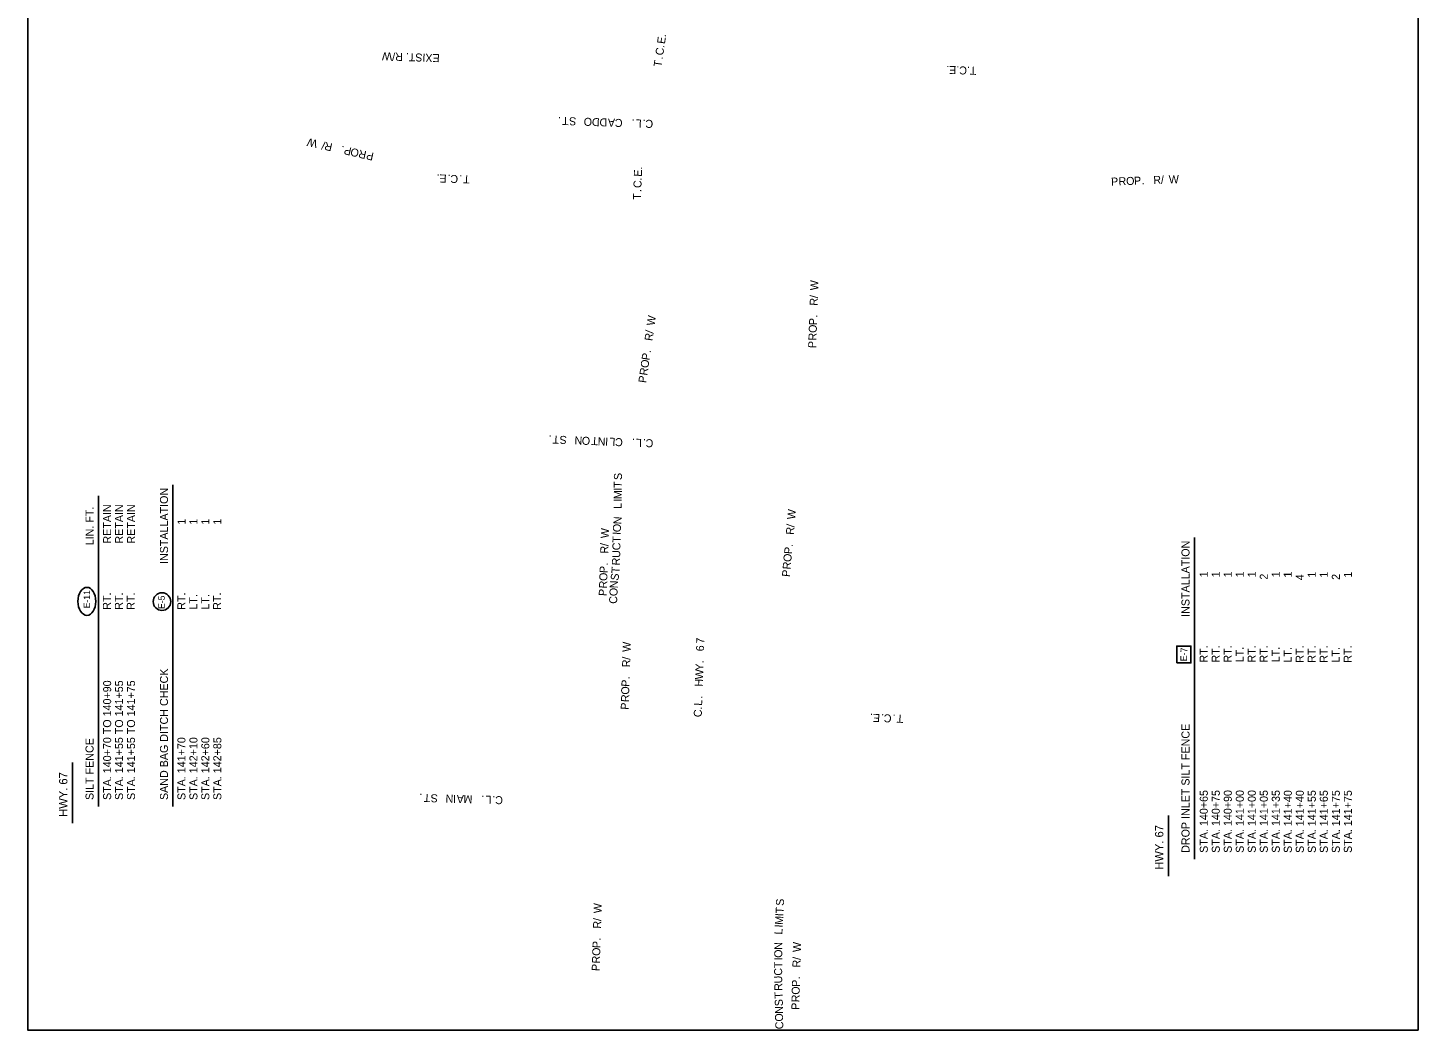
# Model space of a CAD drawing. Extents: x 991974 to 993016, y 1842702 to 1844298.
# Drawn here: x 991974 to 993016, y 1842702 to 1843454 of the extents above; entities that cross this region are included whole.
import ezdxf

# ---------------------------------------------------------------- set-up
doc = ezdxf.new("R2010")
doc.units = 0
for name, color, linetype in [('1', 7, 'Continuous'), ('44', 7, 'Continuous'), ('Default', 7, 'Continuous'), ('R_Draft', 7, 'Continuous')]:
    doc.layers.add(name, color=color, linetype=linetype)

msp = doc.modelspace()

# ---------------------------------------------------------------- linework, layer by layer
at = {"layer": '1'}
msp.add_lwpolyline([(992835.4, 1842977.7), (992835.4, 1842990.4), (992845.9, 1842990.4), (992845.9, 1842977.7)], close=True, dxfattribs=at)
msp.add_circle((992074.6, 1843023.7), 6.61, dxfattribs=at)
msp.add_ellipse((992018.3, 1843023.9), major_axis=(0, 10.5), ratio=0.638788, dxfattribs=at)
at = {"layer": '44'}
for p, q in [((992082.8, 1842870.2), (992082.8, 1843111.2)), ((992027.1, 1842870.2), (992027.1, 1843103)), ((992848.7, 1842830.7), (992848.7, 1843071.7)), ((992007.5, 1842857.6), (992007.5, 1842903.1)), ((992829.1, 1842818), (992829.1, 1842863.5))]:
    msp.add_line(p, q, dxfattribs=at)
at = {"layer": 'Default'}
msp.add_lwpolyline([(993016.3, 1842702.5), (991974, 1842702.5), (991974, 1843999.5), (992023.6, 1843999.5), (992023.6, 1844170.3), (992171.1, 1844170.3), (992171.1, 1844297.8), (993016.3, 1844297.8)], close=True, dxfattribs=at)

# ---------------------------------------------------------------- texts
at = {"layer": '1'}
for s, height, rotation, p in [('E-11', 4.8, 90, (992020.7, 1843018.7)), ('E-5 ', 4.8, 90, (992076.7, 1843018.2)), ('E-7 ', 5, 89.6132, (992843.1, 1842978.9))]:
    msp.add_text(s, height=height, rotation=rotation, dxfattribs=at).set_placement(p)
at = {"layer": '44'}
for s, height, p in [('INSTALLATION', 6, (992079.1, 1843051.9)), ('LIN. FT.', 6, (992023.3, 1843065.9)), ('RETAIN', 6, (992036.5, 1843067.2)), ('RETAIN', 6, (992045.4, 1843067.2)), ('RETAIN', 6, (992054.4, 1843067.2)), ('INSTALLATION', 6, (992844.9, 1843012.3)), ('1', 6, (992858.6, 1843041.9)), ('1', 6, (992867.6, 1843041.9)), ('1', 6, (992876.6, 1843041.9)), ('1', 6, (992885.6, 1843041.9)), ('1', 6, (992894.6, 1843041.9)), ('2', 6, (992903.6, 1843040.2)), ('1', 6, (992912.6, 1843041.9)), ('1', 6, (992921.6, 1843041.9)), ('1', 6, (992921.6, 1843041.7)), ('4', 6, (992930.6, 1843039.7)), ('1', 6, (992939.6, 1843041.7)), ('1', 6, (992948.6, 1843041.7)), ('2', 6, (992957.6, 1843040)), ('1', 6, (992966.6, 1843041.7)), ('RT.', 6, (992036.3, 1843017.6)), ('RT.', 6, (992045.3, 1843017.6)), ('RT.', 6, (992054.2, 1843017.6)), ('RT.', 6, (992858.5, 1842978)), ('RT.', 6, (992867.5, 1842978)), ('RT.', 6, (992876.5, 1842978)), ('LT.', 6, (992957.5, 1842978)), ('SAND BAG DITCH CHECK', 6, (992079.1, 1842875)), ('STA. 140+70 TO 140+90', 6, (992036.5, 1842875)), ('STA. 141+55 TO 141+55', 6, (992045.4, 1842875)), ('STA. 141+55 TO 141+75', 6, (992054.4, 1842875)), ('DROP INLET SILT FENCE', 6, (992844.9, 1842835.4)), ('SILT FENCE      ', 6, (992023.3, 1842875)), ('HWY. 67', 6.25, (992003.7, 1842862.4)), ('HWY. 67', 6.25, (992825.3, 1842822.8))]:
    msp.add_text(s, height=height, rotation=90, dxfattribs=at).set_placement(p)
at = {"layer": 'R_Draft'}
for s, rotation, p in [('.', 81.6819, (992452.3, 1843446.7)), ('C', 81.6819, (992450.3, 1843432.8)), ('E', 81.6819, (992451.6, 1843441.4)), ('.', 81.6819, (992451.1, 1843438.5)), ('EXIST. R/W', 178.0562, (992282.9, 1843434)), ('T', 81.6819, (992449, 1843424.1)), ('.', 81.6819, (992449.9, 1843429.9)), ('T.C.E.', 178.0361, (992685.3, 1843424.5)), ('.', 178.1194, (992373.7, 1843386.9)), ('T', 178.1194, (992379.6, 1843386.8)), ('S', 178.1194, (992385.3, 1843386.6)), ('O', 178.1194, (992397.1, 1843386.2)), ('D', 178.1194, (992402.8, 1843386)), ('D', 178.1194, (992408.5, 1843385.8)), ('A', 178.1194, (992414.3, 1843385.6)), ('C', 178.1194, (992420, 1843385.4)), ('.', 178.1194, (992428.9, 1843385.1)), ('L', 178.1194, (992434.3, 1843385)), ('.', 178.1194, (992437.2, 1843384.9)), ('C', 178.1194, (992442.9, 1843384.7)), ('W', 167.2621, (992191.6, 1843369.5)), ('/', 167.2621, (992197.3, 1843368.2)), ('R', 167.2621, (992202.8, 1843367)), ('.', 167.2621, (992211.5, 1843365)), ('P', 167.2621, (992217.1, 1843363.8)), ('O', 167.2621, (992222.8, 1843362.5)), ('R', 167.2621, (992228.3, 1843361.2)), ('P', 167.2621, (992233.8, 1843360)), ('.', 178.0318, (992282.8, 1843343.9)), ('E', 178.0318, (992288.1, 1843343.7)), ('.', 178.0318, (992291.1, 1843343.6)), ('C', 178.0318, (992296.7, 1843343.4)), ('.', 178.0318, (992299.7, 1843343.3)), ('T', 178.0318, (992305.5, 1843343.1)), ('E', 88.0361, (992434.3, 1843342.1)), ('.', 88.0361, (992434.5, 1843347.5)), ('/', 2.1217, (992823.6, 1843336.9)), ('W', 2.1217, (992829.5, 1843337.1)), ('C', 88.0361, (992434, 1843333.6)), ('.', 88.0361, (992434.2, 1843339.2)), ('P', 2.1217, (992786.2, 1843335.5)), ('R', 2.1217, (992791.8, 1843335.7)), ('O', 2.1217, (992797.5, 1843335.9)), ('P', 2.1217, (992803.4, 1843336.1)), ('.', 2.1217, (992809, 1843336.4)), ('R', 2.1217, (992817.9, 1843336.7)), ('T', 88.0361, (992433.7, 1843324.8)), ('.', 88.0361, (992433.9, 1843330.6)), ('W', 88.0361, (992566.5, 1843256.9)), ('/', 88.0361, (992566.3, 1843251.1)), ('R', 88.0361, (992566.1, 1843245.4)), ('W', 81.6959, (992443.8, 1843230.2)), ('O', 88.0361, (992565.4, 1843225)), ('P', 88.0361, (992565.6, 1843230.8)), ('.', 88.0361, (992565.8, 1843236.5)), ('R', 81.6959, (992442.2, 1843218.8)), ('/', 81.6959, (992443, 1843224.4)), ('P', 88.0361, (992565, 1843213.6)), ('R', 88.0361, (992565.2, 1843219.3)), ('P', 81.6959, (992440, 1843204.3)), ('.', 81.6959, (992440.9, 1843209.9)), ('R', 81.6959, (992438.4, 1843192.9)), ('O', 81.6959, (992439.2, 1843198.5)), ('P', 81.6959, (992437.6, 1843187.3)), ('.', 177.7861, (992366.7, 1843148.2)), ('T', 177.7861, (992372.5, 1843148)), ('S', 177.7861, (992378.2, 1843147.8)), ('N', 177.7861, (992389.8, 1843147.3)), ('O', 177.7861, (992395.7, 1843147.1)), ('T', 177.7861, (992401.5, 1843146.9)), ('N', 177.7861, (992407.2, 1843146.6)), ('I', 177.7861, (992409.2, 1843146.6)), ('L', 177.7861, (992414.6, 1843146.4)), ('C', 177.7861, (992420.2, 1843146.1)), ('.', 177.7861, (992429.2, 1843145.8)), ('L', 177.7861, (992434.5, 1843145.6)), ('.', 177.7861, (992437.5, 1843145.5)), ('C', 177.7861, (992443.1, 1843145.3)), ('S', 89.5494, (992419.4, 1843114.8)), ('T', 89.5494, (992419.3, 1843108.9)), ('I', 89.5494, (992419.3, 1843106.9)), ('M', 89.5494, (992419.3, 1843100.5)), ('L', 89.5494, (992419.2, 1843093.1)), ('I', 89.5494, (992419.3, 1843098.5)), ('W', 84.7809, (992549.2, 1843085.1)), ('1', 90, (992092.3, 1843081.4)), ('1', 90, (992101.2, 1843081.4)), ('1', 90, (992110.1, 1843081.4)), ('1', 90, (992119.1, 1843081.4)), ('N', 86.5403, (992418.9, 1843081.5)), ('W', 88.0361, (992409.5, 1843071.1)), ('T', 88.4991, (992418.3, 1843067.8)), ('I', 86.5403, (992418.4, 1843073.6)), ('O', 86.5403, (992418.5, 1843075.6)), ('R', 84.7809, (992548.2, 1843073.6)), ('/', 84.7809, (992548.7, 1843079.3)), ('/', 88.0361, (992409.3, 1843065.2)), ('R', 88.0361, (992409.1, 1843059.6)), ('U', 88.6784, (992418.1, 1843056.4)), ('C', 88.6784, (992418.2, 1843062.1)), ('P', 84.7809, (992546.9, 1843059.1)), ('.', 84.7809, (992547.4, 1843064.7)), ('.', 88.0361, (992408.8, 1843050.7)), ('R', 87.356, (992417.8, 1843050.7)), ('R', 84.7809, (992545.8, 1843047.6)), ('O', 84.7809, (992546.3, 1843053.2)), ('O', 88.0361, (992408.4, 1843039.1)), ('P', 88.0361, (992408.6, 1843045)), ('S', 81.8039, (992416.7, 1843039.2)), ('T', 87.356, (992417.5, 1843044.8)), ('P', 84.7809, (992545.3, 1843042)), ('P', 88.0361, (992408, 1843027.8)), ('R', 88.0361, (992408.2, 1843033.5)), ('O', 87.8121, (992416, 1843027.7)), ('N', 87.8121, (992416.2, 1843033.6)), ('RT.', 90, (992092.1, 1843017.6)), ('LT.', 90, (992101, 1843017.7)), ('LT.', 90, (992110, 1843017.7)), ('RT.', 90, (992118.9, 1843017.6)), ('C', 90.2615, (992415.9, 1843022.1)), ('W', 88.2135, (992425.8, 1842985.9)), ('6', 88.0361, (992480.9, 1842986.4)), ('7', 88.0361, (992481.1, 1842992.1)), ('LT.', 90, (992885.5, 1842978.2)), ('RT.', 90, (992894.5, 1842978)), ('RT.', 90, (992903.5, 1842978)), ('LT.', 90, (992912.5, 1842978.2)), ('LT.', 90, (992921.5, 1842978)), ('RT.', 90, (992930.5, 1842977.9)), ('RT.', 90, (992939.5, 1842977.9)), ('RT.', 90, (992948.5, 1842977.9)), ('RT.', 90, (992966.5, 1842977.9)), ('/', 88.2135, (992425.7, 1842980)), ('R', 88.2135, (992425.5, 1842974.4)), ('.', 88.0361, (992480.6, 1842977.5)), ('W', 88.0361, (992480.2, 1842965.3)), ('Y', 88.0361, (992480.4, 1842971.8)), ('O', 88.2135, (992424.8, 1842953.9)), ('P', 88.2135, (992425, 1842959.8)), ('.', 88.2135, (992425.2, 1842965.5)), ('H', 88.0361, (992480, 1842959.9)), ('P', 88.2135, (992424.5, 1842942.6)), ('R', 88.2135, (992424.7, 1842948.3)), ('L', 88.0361, (992479.5, 1842945.6)), ('.', 88.0361, (992479.7, 1842951)), ('C', 88.0361, (992479.2, 1842937)), ('.', 88.0361, (992479.4, 1842942.7)), ('.', 178.0361, (992607.7, 1842939.6)), ('E', 178.0361, (992613, 1842939.4)), ('.', 178.0361, (992616, 1842939.3)), ('C', 178.0361, (992621.6, 1842939.1)), ('.', 178.0361, (992624.6, 1842939)), ('T', 178.0361, (992630.4, 1842938.8)), ('STA. 141+70', 90, (992092.2, 1842875)), ('STA. 142+10', 90, (992101.2, 1842875)), ('STA. 142+60', 90, (992110.1, 1842875)), ('STA. 142+85', 90, (992119.1, 1842875)), ('.', 178.3694, (992269.9, 1842879.6)), ('T', 178.3694, (992275.8, 1842879.4)), ('S', 178.3694, (992281.5, 1842879.2)), ('N', 178.3694, (992293.1, 1842878.9)), ('I', 178.3694, (992295.1, 1842878.8)), ('A', 178.3694, (992301, 1842878.7)), ('M', 178.3694, (992307.4, 1842878.5)), ('.', 178.3694, (992316.3, 1842878.2)), ('L', 178.3694, (992321.7, 1842878.1)), ('.', 178.3694, (992324.6, 1842878)), ('C', 178.3694, (992330.3, 1842877.8)), ('STA. 140+65', 90, (992858.6, 1842835.4)), ('STA. 140+75', 90, (992867.6, 1842835.4)), ('STA. 140+90', 90, (992876.6, 1842835.4)), ('STA. 141+00', 90, (992885.6, 1842835.4)), ('STA. 141+00', 90, (992894.6, 1842835.4)), ('STA. 141+05', 90, (992903.6, 1842835.4)), ('STA. 141+35', 90, (992912.6, 1842835.4)), ('STA. 141+40', 90, (992921.6, 1842835.3)), ('STA. 141+40', 90, (992930.6, 1842835.3)), ('STA. 141+55', 90, (992939.6, 1842835.3)), ('STA. 141+65', 90, (992948.6, 1842835.3)), ('STA. 141+75', 90, (992957.6, 1842835.3)), ('STA. 141+75', 90, (992966.6, 1842835.3)), ('W', 88.2135, (992404.1, 1842790)), ('T', 87.447, (992540.6, 1842789.8)), ('S', 87.447, (992540.8, 1842795.6)), ('/', 88.2135, (992403.9, 1842784.2)), ('R', 88.2135, (992403.7, 1842778.5)), ('I', 86.5651, (992539.9, 1842779.3)), ('M', 86.5651, (992540, 1842781.3)), ('I', 86.5651, (992540.4, 1842787.7)), ('.', 88.2135, (992403.4, 1842769.6)), ('L', 86.6234, (992539.6, 1842774)), ('O', 88.2135, (992403.1, 1842758.1)), ('P', 88.2135, (992403.3, 1842763.9)), ('O', 89.4756, (992539.6, 1842756.7)), ('N', 91.0531, (992539.7, 1842762.8)), ('W', 88.2437, (992553.5, 1842760.9)), ('P', 88.2135, (992402.7, 1842746.7)), ('R', 88.2135, (992402.9, 1842752.4)), ('I', 89.4756, (992539.6, 1842754.8)), ('T', 89.7917, (992539.6, 1842748.9)), ('/', 88.3031, (992553.3, 1842755.1)), ('R', 88.3605, (992553.2, 1842749.4)), ('C', 89.7917, (992539.5, 1842743.3)), ('U', 90.9799, (992539.6, 1842737.6)), ('P', 88.5084, (992552.8, 1842734.9)), ('.', 88.4509, (992552.9, 1842740.5)), ('R', 91.1023, (992539.7, 1842732)), ('T', 91.663, (992539.9, 1842726.2)), ('R', 88.6251, (992552.5, 1842723.3)), ('O', 88.5677, (992552.6, 1842729)), ('S', 91.663, (992540.1, 1842720.5)), ('N', 91.1824, (992540.2, 1842714.8)), ('P', 88.6826, (992552.4, 1842717.7)), ('O', 91.8951, (992540.3, 1842709)), ('C', 91.8951, (992540.5, 1842703.3))]:
    msp.add_text(s, height=6, rotation=rotation, dxfattribs=at).set_placement(p)

doc.saveas('drawing.dxf')
